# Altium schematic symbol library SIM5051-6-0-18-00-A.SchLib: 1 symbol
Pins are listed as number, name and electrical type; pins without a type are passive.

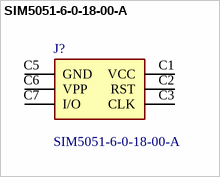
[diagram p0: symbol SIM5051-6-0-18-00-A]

## SIM5051-6-0-18-00-A
designator J?
Memory Card Connectors SIM Card ConnectorHinged Type, 6 Pin, SMT, 1.85mm Profile; Manufacturer_Name: GCT (GLOBAL CONNECTOR TECHNOLOGY); Geometry.Height: 2mm
footprint SIM5051601800A
pins: C1 VCC, C2 RST, C3 CLK, C5 GND, C6 VPP, C7 I/O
